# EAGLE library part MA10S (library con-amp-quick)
AMP QUICK CONNECTOR
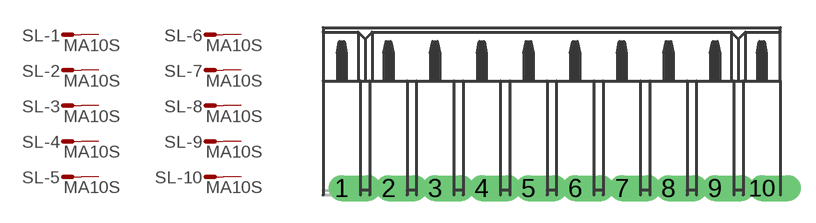
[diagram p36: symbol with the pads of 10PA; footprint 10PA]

Designator prefix SL; gates -1=M -2=M -3=M -4=M -5=M -6=M -7=M -8=M -9=M -10=M

## MA10S  [10PA]
1  -1:S  pas
2  -2:S  pas
3  -3:S  pas
4  -4:S  pas
5  -5:S  pas
6  -6:S  pas
7  -7:S  pas
8  -8:S  pas
9  -9:S  pas
10  -10:S  pas

## Footprint 10PA (pad centres in mm)
AMP QUICK CONNECTOR
drill 0.914 offset: 1 -11.43,0; 2 -8.89,0; 3 -6.35,0; 4 -3.81,0; 5 -1.27,0; 6 1.27,0; 7 3.81,0; 8 6.35,0; 9 8.89,0; 10 11.43,0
